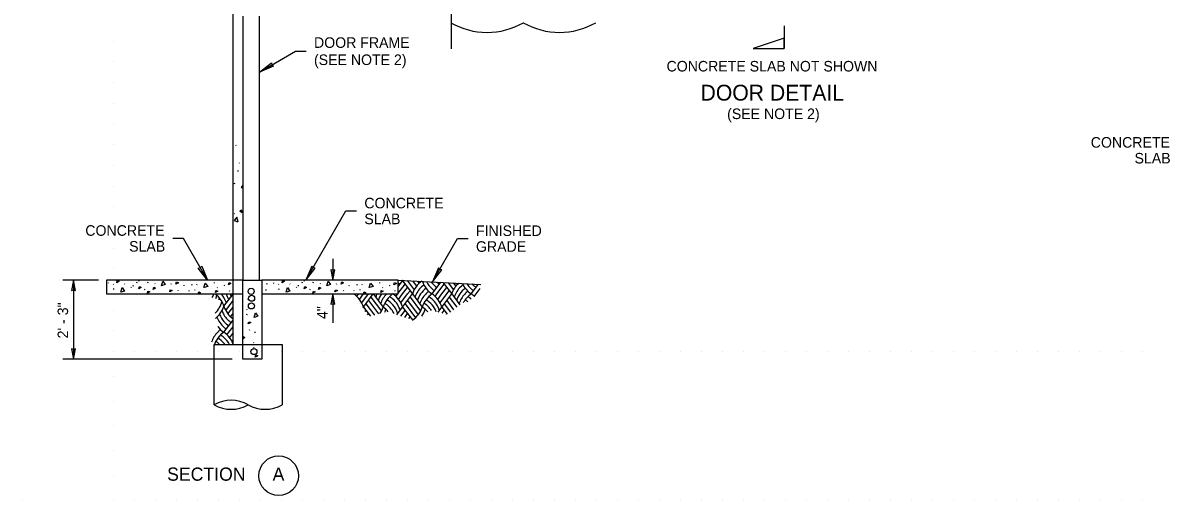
# Model space of a CAD drawing. Extents: x 99862 to 103151, y 100000 to 102076.
# Drawn here: x 99862 to 101581, y 100000 to 100723 of the extents above; entities that cross this region are included whole.
import ezdxf

# ---------------------------------------------------------------- set-up
doc = ezdxf.new("R2010")
doc.units = 0
for name, color, linetype in [('Level 1', 7, 'Continuous'), ('Level 13', 7, 'Continuous'), ('Level 15', 7, 'Continuous'), ('Level 16', 7, 'Continuous'), ('Level 17', 7, 'Continuous'), ('Level 20', 7, 'Continuous'), ('Level 22', 7, 'Continuous'), ('Level 60', 7, 'Continuous'), ('Level 8', 7, 'Continuous'), ('Level 9', 7, 'Continuous')]:
    doc.layers.add(name, color=color, linetype=linetype)

msp = doc.modelspace()

# ---------------------------------------------------------------- linework, layer by layer
at = {"layer": 'Level 1'}
for p, q in [((100000, 100695.3), (100000, 100695.3)), ((100000, 100664), (100000, 100664)), ((100000, 100632.6), (100000, 100632.6)), ((100000, 100601.3), (100000, 100601.3)), ((100000, 100569.9), (100000, 100569.9)), ((100000, 100538.6), (100000, 100538.6)), ((100000, 100507.2), (100000, 100507.2)), ((100000, 100475.8), (100000, 100475.8)), ((100000, 100444.5), (100000, 100444.5)), ((100000, 100413.1), (100000, 100413.1)), ((100000, 100381.8), (100000, 100381.8)), ((100000, 100350.4), (100000, 100350.4)), ((100000, 100319.1), (100000, 100319.1)), ((100000, 100287.7), (100000, 100287.7)), ((100000, 100256.4), (100000, 100256.4)), ((100000, 100225), (100000, 100225)), ((100031.8, 100225), (100031.8, 100225)), ((100063.6, 100225), (100063.6, 100225)), ((100095.5, 100225), (100095.5, 100225)), ((100127.3, 100225), (100127.3, 100225)), ((100159.1, 100225), (100159.1, 100225)), ((100190.9, 100225), (100190.9, 100225)), ((100222.7, 100225), (100222.7, 100225)), ((100254.5, 100225), (100254.5, 100225)), ((100286.4, 100225), (100286.4, 100225)), ((100318.2, 100225), (100318.2, 100225)), ((100350, 100225), (100350, 100225)), ((100381.8, 100225), (100381.8, 100225)), ((100413.6, 100225), (100413.6, 100225)), ((100445.5, 100225), (100445.5, 100225)), ((100477.3, 100225), (100477.3, 100225)), ((100509.1, 100225), (100509.1, 100225)), ((100540.9, 100225), (100540.9, 100225)), ((100572.7, 100225), (100572.7, 100225)), ((100604.5, 100225), (100604.5, 100225)), ((100636.4, 100225), (100636.4, 100225)), ((100668.2, 100225), (100668.2, 100225)), ((100700, 100225), (100700, 100225)), ((100731.8, 100225), (100731.8, 100225)), ((100763.6, 100225), (100763.6, 100225)), ((100795.5, 100225), (100795.5, 100225)), ((100827.3, 100225), (100827.3, 100225)), ((100859.1, 100225), (100859.1, 100225)), ((100890.9, 100225), (100890.9, 100225)), ((100922.7, 100225), (100922.7, 100225)), ((100954.5, 100225), (100954.5, 100225)), ((100986.4, 100225), (100986.4, 100225)), ((101018.2, 100225), (101018.2, 100225)), ((101050, 100225), (101050, 100225)), ((101081.8, 100225), (101081.8, 100225)), ((101113.6, 100225), (101113.6, 100225)), ((101145.5, 100225), (101145.5, 100225)), ((101177.3, 100225), (101177.3, 100225)), ((101209.1, 100225), (101209.1, 100225)), ((101240.9, 100225), (101240.9, 100225)), ((101272.7, 100225), (101272.7, 100225)), ((101304.5, 100225), (101304.5, 100225)), ((101336.4, 100225), (101336.4, 100225)), ((101368.2, 100225), (101368.2, 100225)), ((101400, 100225), (101400, 100225)), ((101431.8, 100225), (101431.8, 100225)), ((101463.6, 100225), (101463.6, 100225)), ((101495.5, 100225), (101495.5, 100225)), ((101527.3, 100225), (101527.3, 100225)), ((101559.1, 100225), (101559.1, 100225)), ((100000, 100187.5), (100000, 100187.5)), ((100000, 100150), (100000, 100150)), ((100000, 100112.5), (100000, 100112.5)), ((100000, 100075), (100000, 100075)), ((100000, 100037.5), (100000, 100037.5)), ((100000, 100000), (100000, 100000)), ((100031.8, 100000), (100031.8, 100000)), ((100063.6, 100000), (100063.6, 100000)), ((100095.5, 100000), (100095.5, 100000)), ((100127.3, 100000), (100127.3, 100000)), ((100159.1, 100000), (100159.1, 100000)), ((100190.9, 100000), (100190.9, 100000)), ((100222.7, 100000), (100222.7, 100000)), ((100254.5, 100000), (100254.5, 100000)), ((100286.4, 100000), (100286.4, 100000)), ((100318.2, 100000), (100318.2, 100000)), ((100350, 100000), (100350, 100000)), ((100381.8, 100000), (100381.8, 100000)), ((100413.6, 100000), (100413.6, 100000)), ((100445.5, 100000), (100445.5, 100000)), ((100477.3, 100000), (100477.3, 100000)), ((100509.1, 100000), (100509.1, 100000)), ((100540.9, 100000), (100540.9, 100000)), ((100572.7, 100000), (100572.7, 100000)), ((100604.5, 100000), (100604.5, 100000)), ((100636.4, 100000), (100636.4, 100000)), ((100668.2, 100000), (100668.2, 100000)), ((100700, 100000), (100700, 100000)), ((100731.8, 100000), (100731.8, 100000)), ((100763.6, 100000), (100763.6, 100000)), ((100795.5, 100000), (100795.5, 100000)), ((100827.3, 100000), (100827.3, 100000)), ((100859.1, 100000), (100859.1, 100000)), ((100890.9, 100000), (100890.9, 100000)), ((100922.7, 100000), (100922.7, 100000)), ((100954.5, 100000), (100954.5, 100000)), ((100986.4, 100000), (100986.4, 100000)), ((101018.2, 100000), (101018.2, 100000)), ((101050, 100000), (101050, 100000)), ((101081.8, 100000), (101081.8, 100000)), ((101113.6, 100000), (101113.6, 100000)), ((101145.5, 100000), (101145.5, 100000)), ((101177.3, 100000), (101177.3, 100000)), ((101209.1, 100000), (101209.1, 100000)), ((101240.9, 100000), (101240.9, 100000)), ((101272.7, 100000), (101272.7, 100000)), ((101304.5, 100000), (101304.5, 100000)), ((101336.4, 100000), (101336.4, 100000)), ((101368.2, 100000), (101368.2, 100000)), ((101400, 100000), (101400, 100000)), ((101431.8, 100000), (101431.8, 100000)), ((101463.6, 100000), (101463.6, 100000)), ((101495.5, 100000), (101495.5, 100000)), ((101527.3, 100000), (101527.3, 100000)), ((101559.1, 100000), (101559.1, 100000))]:
    msp.add_line(p, q, dxfattribs=at)
at = {"layer": 'Level 13'}
for centre in [(100208.4, 100316.2), (100209, 100305.7), (100208.8, 100294.1), (100212.5, 100224.9)]:
    msp.add_circle(centre, 4.63, dxfattribs=at)
at = {"layer": 'Level 15'}
for p, q in [((100220.9, 100648.5), (100275.7, 100680.2)), ((100275.7, 100680.2), (100291.7, 100680.2)), ((100291.5, 100333.3), (100352, 100438)), ((100352, 100438), (100368, 100438)), ((100105.8, 100396.4), (100089.8, 100396.4)), ((100142.2, 100333.3), (100105.8, 100396.4)), ((100483.4, 100330.6), (100521.2, 100396.1)), ((100521.2, 100396.1), (100537.2, 100396.1)), ((100332.3, 100365.3), (100332.3, 100333.3)), ((99977.1, 100333.3), (99922.9, 100333.3)), ((99938.9, 100333.3), (99938.9, 100213.3)), ((100332.3, 100312.4), (100332.3, 100268.4)), ((100179.5, 100213.3), (99922.9, 100213.3))]:
    msp.add_line(p, q, dxfattribs=at)
msp.add_lwpolyline([(100511.7, 101508.6), (100511.7, 101074.6), (100527.2, 101074.6), (100496.2, 101043.6), (100511.7, 101043.6), (100511.7, 100683.8)], dxfattribs=at)
for points in [[(100220.9, 100648.5), (100239.2, 100662.5), (100239.7, 100659.4), (100242.1, 100657.3)], [(100142.2, 100333.3), (100128.2, 100351.5), (100131.4, 100352.1), (100133.4, 100354.5)], [(100291.5, 100333.3), (100305.5, 100351.5), (100302.4, 100352.1), (100300.3, 100354.5)], [(100332.3, 100333.3), (100335.4, 100349), (100332.3, 100348.3), (100329.3, 100349)], [(100483.4, 100330.6), (100497.4, 100348.8), (100494.3, 100349.4), (100492.2, 100351.8)], [(99938.9, 100333.3), (99935.8, 100317.5), (99938.9, 100318.3), (99942, 100317.5)], [(100332.3, 100312.4), (100329.3, 100296.6), (100332.3, 100297.4), (100335.4, 100296.6)], [(99938.9, 100213.3), (99942, 100229), (99938.9, 100228.3), (99935.8, 100229)]]:
    msp.add_lwpolyline(points, close=True, dxfattribs=at)
at = {"layer": 'Level 16'}
for p, q in [((100185.5, 100536.5), (100185.2, 100537.7)), ((100188.9, 100497.9), (100188.6, 100499.1)), ((100183.5, 100478.7), (100183.3, 100479.9)), ((100183.1, 100434.3), (100182.5, 100433.7)), ((99991.4, 100329.2), (99992, 100328.6)), ((99999.2, 100327.3), (99999.9, 100326.7)), ((100016.3, 100327.7), (100016.9, 100327)), ((100026.6, 100321.8), (100026.8, 100323)), ((100029.5, 100324.2), (100029.8, 100325.4)), ((100035.3, 100329.2), (100035.5, 100330.4)), ((100038.2, 100331.6), (100038.5, 100332.8)), ((100051.9, 100329.3), (100052.1, 100330.5)), ((100062.2, 100328.2), (100062.9, 100327.6)), ((100086.6, 100327.9), (100087.3, 100327.3)), ((100106.6, 100324.4), (100106.8, 100325.6)), ((100118.6, 100325.7), (100118.9, 100326.9)), ((100126.1, 100325.9), (100126.3, 100327.1)), ((100152.6, 100328.6), (100152.9, 100329.8)), ((100156.9, 100322.2), (100157.5, 100321.6)), ((100167.2, 100325.5), (100167.8, 100324.9)), ((100232.4, 100327.3), (100232.7, 100328.5)), ((100242, 100329.2), (100242.6, 100328.6)), ((100249.9, 100327.3), (100250.5, 100326.7)), ((100266.9, 100327.7), (100267.5, 100327)), ((100277.2, 100321.8), (100277.4, 100323)), ((100280.2, 100324.2), (100280.4, 100325.4)), ((100285.9, 100329.2), (100286.2, 100330.4)), ((100288.9, 100331.6), (100289.1, 100332.8)), ((100302.5, 100329.3), (100302.8, 100330.5)), ((100312.9, 100328.2), (100313.5, 100327.6)), ((100337.3, 100327.9), (100337.9, 100327.3)), ((100357.2, 100324.4), (100357.5, 100325.6)), ((100369.3, 100325.7), (100369.5, 100326.9)), ((100376.7, 100325.9), (100377, 100327.1)), ((100403.3, 100328.6), (100403.5, 100329.8)), ((100407.5, 100322.2), (100408.1, 100321.6)), ((100417.8, 100325.5), (100418.5, 100324.9)), ((100000, 100319.1), (100000.3, 100320.3)), ((100046.4, 100319.6), (100047, 100319)), ((100097.8, 100317), (100098.1, 100318.2)), ((100113.5, 100317.4), (100114.2, 100316.8)), ((100123, 100317.8), (100123.3, 100319)), ((100175.8, 100316.4), (100176.1, 100317.6)), ((100203.6, 100303.8), (100203.9, 100305)), ((100231.1, 100317.6), (100231.4, 100318.8)), ((100250.6, 100319.1), (100250.9, 100320.3)), ((100297, 100319.6), (100297.7, 100319)), ((100348.5, 100317), (100348.7, 100318.2)), ((100364.2, 100317.4), (100364.8, 100316.8)), ((100373.7, 100317.8), (100373.9, 100319)), ((100426.5, 100316.4), (100426.7, 100317.6)), ((100201.2, 100289), (100201.8, 100288.4)), ((100202, 100280.8), (100202.2, 100282)), ((100205.4, 100258.3), (100205.7, 100257.2)), ((100214.3, 100253.4), (100214.6, 100254.6)), ((100211.9, 100238.7), (100212.5, 100238.1)), ((100212.7, 100230.5), (100212.9, 100231.7))]:
    msp.add_line(p, q, dxfattribs=at)
for points in [[(100190.4, 100510.9), (100190, 100510.7), (100190.4, 100510.5)], [(100195.9, 100477), (100193.5, 100473.7), (100195.9, 100473)], [(100188.5, 100421.6), (100186.6, 100428.5), (100182.8, 100423.4), (100188.4, 100421.7)], [(100194.7, 100435.9), (100193.9, 100439.3), (100191.1, 100438), (100194.7, 100435.9)], [(100004.6, 100329.3), (100005.4, 100332.7), (100008.2, 100331.4), (100004.6, 100329.3)], [(100010.8, 100315), (100012.8, 100321.9), (100016.6, 100316.7), (100011, 100315)], [(100038.2, 100320.2), (100039, 100323.5), (100041.8, 100322.2), (100038.2, 100320.2)], [(100059.8, 100319.2), (100060.6, 100322.5), (100063.5, 100321.2), (100059.8, 100319.2)], [(100072.4, 100324.7), (100074.3, 100331.6), (100078.1, 100326.4), (100072.5, 100324.7)], [(100094.4, 100327.2), (100095.2, 100330.6), (100098, 100329.3), (100094.4, 100327.2)], [(100136.9, 100321.8), (100138.9, 100328.7), (100142.6, 100323.6), (100137, 100321.9)], [(100174.2, 100326.2), (100175, 100329.6), (100177.8, 100328.3), (100174.2, 100326.2)], [(100255.3, 100329.3), (100256.1, 100332.7), (100258.9, 100331.4), (100255.3, 100329.3)], [(100261.5, 100315), (100263.4, 100321.9), (100267.2, 100316.7), (100261.6, 100315)], [(100288.8, 100320.2), (100289.6, 100323.5), (100292.5, 100322.2), (100288.8, 100320.2)], [(100310.5, 100319.2), (100311.3, 100322.5), (100314.1, 100321.2), (100310.5, 100319.2)], [(100323, 100324.7), (100325, 100331.6), (100328.7, 100326.4), (100323.1, 100324.7)], [(100345, 100327.2), (100345.8, 100330.6), (100348.6, 100329.3), (100345, 100327.2)], [(100387.5, 100321.8), (100389.5, 100328.7), (100393.3, 100323.6), (100387.7, 100321.9)], [(100424.8, 100326.2), (100425.6, 100329.6), (100428.5, 100328.3), (100424.8, 100326.2)], [(100051.2, 100313.3), (100052, 100316.6), (100054.8, 100315.3), (100051.2, 100313.3)], [(100084.9, 100315.4), (100085.7, 100318.7), (100088.5, 100317.4), (100084.9, 100315.4)], [(100128.1, 100312), (100129, 100315.3), (100131.8, 100314), (100128.1, 100312)], [(100154.2, 100314.3), (100155, 100317.7), (100157.8, 100316.4), (100154.2, 100314.3)], [(100301.9, 100313.3), (100302.7, 100316.6), (100305.5, 100315.3), (100301.9, 100313.3)], [(100335.5, 100315.4), (100336.3, 100318.7), (100339.1, 100317.4), (100335.5, 100315.4)], [(100378.8, 100312), (100379.6, 100315.3), (100382.4, 100314), (100378.8, 100312)], [(100404.8, 100314.3), (100405.6, 100317.7), (100408.4, 100316.4), (100404.8, 100314.3)], [(100204, 100266.9), (100204.8, 100270.2), (100207.7, 100268.9), (100204, 100266.9)], [(100212.8, 100276.8), (100214.8, 100283.6), (100218.5, 100278.5), (100212.9, 100276.8)], [(100196.2, 100248), (100198.9, 100246.2), (100196.3, 100244.2)], [(100214.7, 100216.6), (100215.5, 100219.9), (100218.4, 100218.6), (100214.7, 100216.6)]]:
    msp.add_lwpolyline(points, dxfattribs=at)
at = {"layer": 'Level 17'}
for p, q in [((100220.9, 100333.3), (100220.9, 100733.3)), ((100180.9, 100235.5), (100180.9, 100333.3))]:
    msp.add_line(p, q, dxfattribs=at)
for points in [[(100195.9, 100333.3), (100180.9, 100333.3), (100180.9, 100743.3)], [(100195.9, 100733.3), (100195.9, 100333.3)], [(100195.9, 100333.3), (99989.1, 100333.3), (99989.1, 100312.4), (100196.1, 100312.4)], [(100195.9, 100213.3), (100195.9, 100333.3), (100224.5, 100333.3), (100224.5, 100213.3), (100195.9, 100213.3)], [(100152.4, 100144.3), (100152.4, 100235.5), (100255.3, 100235.5), (100255.3, 100144.3)]]:
    msp.add_lwpolyline(points, dxfattribs=at)
msp.add_lwpolyline([(100431.5, 100333.3), (100224.5, 100333.3), (100224.5, 100312.4), (100431.5, 100312.4)], close=True, dxfattribs=at)
for centre, radius, start, end in [((100566, 100818.7), 110.1, 240, 300), ((100676, 100818.7), 110.1, 240, 300), ((100178.1, 100099.7), 51.4, 60, 120), ((100178.1, 100188.8), 51.4, 240, 300), ((100229.6, 100188.8), 51.4, 240, 300)]:
    msp.add_arc(centre, radius, start, end, dxfattribs=at)
at = {"layer": 'Level 22'}
for p, q in [((100431.5, 100323.2), (100438.1, 100332)), ((100431.5, 100313.3), (100441.9, 100327)), ((100438.1, 100332), (100438.8, 100332.9)), ((100438.1, 100332), (100453, 100312.2)), ((100438.1, 100312.2), (100445.6, 100322.1)), ((100445.1, 100332.5), (100455.7, 100318.5)), ((100452.9, 100332.1), (100459.1, 100323.8)), ((100460.6, 100331.7), (100463.2, 100328.3)), ((100482.7, 100312.2), (100496, 100329.9)), ((100490.1, 100312.2), (100501.2, 100327)), ((100497.5, 100312.2), (100505, 100322.1)), ((100499.2, 100329.7), (100512.4, 100312.2)), ((100506.9, 100329.3), (100515.1, 100318.5)), ((100514.7, 100328.9), (100518.5, 100323.8)), ((100522.4, 100328.5), (100522.6, 100328.3)), ((100542.1, 100312.2), (100553.1, 100326.9)), ((100167.1, 100293.7), (100180.9, 100312.1)), ((100368.5, 100308.5), (100371.3, 100312.2)), ((100371.3, 100312.2), (100371.3, 100312.2)), ((100372.6, 100304), (100378.7, 100312.2)), ((100376.1, 100298.7), (100386.2, 100312.2)), ((100378.7, 100292.4), (100393.6, 100312.2)), ((100378.7, 100312.2), (100378.8, 100312.2)), ((100386.2, 100312.2), (100386.2, 100312.2)), ((100389.9, 100307.2), (100405.8, 100286.1)), ((100393.5, 100312.3), (100393.6, 100312.2)), ((100393.6, 100312.2), (100408.4, 100292.4)), ((100423.3, 100312.2), (100423.4, 100312.3)), ((100427.9, 100308.5), (100430.7, 100312.2)), ((100430.7, 100312.2), (100430.9, 100312.4)), ((100432, 100304), (100438.1, 100312.2)), ((100435.5, 100298.7), (100445.6, 100312.2)), ((100438.1, 100292.4), (100453, 100312.2)), ((100445.6, 100312.2), (100449.3, 100317.1)), ((100449.3, 100307.2), (100465.2, 100286.1)), ((100453, 100312.2), (100467.8, 100292.4)), ((100487.3, 100308.5), (100490.1, 100312.2)), ((100491.4, 100304), (100497.5, 100312.2)), ((100494.9, 100298.7), (100505, 100312.2)), ((100497.5, 100292.4), (100512.4, 100312.2)), ((100505, 100312.2), (100508.7, 100317.1)), ((100508.7, 100307.2), (100520, 100292.2)), ((100512.4, 100312.2), (100524.6, 100295.9)), ((100546.7, 100308.5), (100549.5, 100312.2)), ((100549.5, 100312.2), (100555.8, 100320.6)), ((100169.8, 100287.3), (100180.9, 100302.2)), ((100173.2, 100282), (100180.9, 100292.3)), ((100377.8, 100291.1), (100378.7, 100292.4)), ((100378.7, 100292.4), (100389.3, 100278.4)), ((100381.2, 100285.8), (100382.5, 100287.4)), ((100382.5, 100297.3), (100395.4, 100280.1)), ((100386.2, 100302.3), (100401.5, 100281.9)), ((100429.5, 100280.8), (100438.1, 100292.4)), ((100435.4, 100278.8), (100441.9, 100287.4)), ((100438.1, 100292.4), (100452.8, 100272.9)), ((100441.9, 100297.3), (100457.6, 100276.3)), ((100445.6, 100302.3), (100461.7, 100280.7)), ((100491.8, 100284.7), (100497.5, 100292.4)), ((100497.5, 100292.4), (100505.7, 100281.5)), ((100498.1, 100283.3), (100501.2, 100287.4)), ((100501.2, 100297.3), (100510.8, 100284.6)), ((100505, 100302.3), (100515.4, 100288.4)), ((100167.1, 100254.1), (100180.9, 100272.5)), ((100177.3, 100277.6), (100180.9, 100282.4)), ((100384.7, 100280.5), (100386.2, 100282.5)), ((100441.3, 100276.8), (100445.6, 100282.5)), ((100447.2, 100274.8), (100449.3, 100277.5)), ((100504.4, 100281.8), (100505, 100282.5)), ((100171.7, 100250.4), (100174.5, 100254.1)), ((100174.5, 100254.1), (100180.9, 100262.6)), ((100175.8, 100245.9), (100180.9, 100252.7)), ((100179.3, 100240.6), (100180.9, 100242.8))]:
    msp.add_line(p, q, dxfattribs=at)
for centre, start, end in [((99967.9, 100302.1), 56.0952, 56.0963), ((100218.6, 100302.1), 56.0952, 56.0963), ((100455.4, 100358.2), 230.574, 236.0964), ((100459.1, 100363.2), 233.4561, 236.0964), ((100488.8, 100300.8), 125.4423, 162.3566), ((100492.5, 100295.8), 126.3063, 154.2266), ((100503.6, 100343.4), 198.6509, 236.0964), ((100507.4, 100348.3), 207.3703, 228.9599), ((100511.1, 100353.3), 216.9567, 220.9416), ((100511.1, 100353.3), 220.9415, 236.0964), ((100514.8, 100358.2), 228.1518, 236.0964), ((100548.2, 100300.8), 132.4757, 162.3566), ((100551.9, 100295.8), 126.3063, 154.2266), ((100563, 100343.4), 203.8023, 236.0964), ((100566.8, 100348.3), 212.9827, 228.9599), ((100570.5, 100353.3), 223.3983, 236.0964), ((100116.4, 100324.8), 331.5641, 340.7064), ((100131.3, 100282.3), 32.4879, 52.8045), ((100120.1, 100319.9), 336.9798, 345.0113), ((100123.9, 100314.9), 342.3545, 346.3199), ((100135, 100287.2), 31.3316, 41.6055), ((100135, 100287.2), 17.6434, 31.3317), ((100138.7, 100292.2), 17.6434, 32.5049), ((100142.4, 100297.1), 17.6434, 23.6581), ((100342.9, 100281), 17.6434, 56.0948), ((100429.4, 100300.8), 162.227, 162.3566), ((100433.1, 100295.8), 154.2265, 162.3566), ((100433.1, 100295.8), 154.063, 154.2266), ((100436.8, 100290.9), 145.491, 162.3566), ((100440.5, 100285.9), 135.7127, 162.3566), ((100436.8, 100290.9), 145.2788, 145.4911), ((100444.3, 100281), 123.9036, 162.3566), ((100440.5, 100285.9), 135.4226, 135.7128), ((100398.6, 100276), 48.9597, 58.5465), ((100444.3, 100343.4), 235.6582, 236.0964), ((100402.3, 100281), 17.6434, 56.0963), ((100398.6, 100276), 17.6434, 48.9597), ((100492.5, 100295.8), 154.2265, 162.3566), ((100496.2, 100290.9), 145.491, 162.3566), ((100499.9, 100285.9), 135.7127, 162.3566), ((100496.2, 100290.9), 127.1006, 145.4911), ((100503.6, 100281), 123.9036, 162.3566), ((100499.9, 100285.9), 126.331, 135.7128), ((100458, 100276), 48.9597, 58.5465), ((100507.4, 100348.3), 228.9599, 236.0964), ((100461.7, 100281), 17.6434, 56.0963), ((100458, 100276), 17.6434, 48.9597), ((100551.9, 100295.8), 154.2265, 162.3566), ((100555.6, 100290.9), 145.491, 162.3566), ((100559.3, 100285.9), 135.7127, 162.3566), ((100555.6, 100290.9), 127.1006, 145.4911), ((100563, 100281), 123.9036, 151.2939), ((100559.3, 100285.9), 126.331, 135.7128), ((100517.4, 100276), 48.9597, 58.5465), ((100566.8, 100348.3), 228.9599, 236.0964), ((100521.1, 100281), 46.5026, 56.0963), ((100127.6, 100310), 314.0469, 345.7713), ((100131.3, 100305), 307.6535, 342.3566), ((100131.3, 100282.3), 17.6434, 31.7715), ((100202.9, 100305), 197.6435, 234.1378), ((100372.6, 100303.8), 325.581, 342.3566), ((100387.5, 100261.2), 39.8941, 56.0964), ((100391.2, 100266.1), 31.3316, 58.4874), ((100376.3, 100298.8), 337.962, 345.0113), ((100394.9, 100271.1), 40.9413, 59.3021), ((100394.9, 100271.1), 17.6434, 40.9414), ((100432, 100303.8), 304.3124, 342.3566), ((100435.7, 100298.8), 327.3344, 345.0113), ((100446.9, 100261.2), 39.2778, 56.0964), ((100450.6, 100266.1), 33.8326, 58.4874), ((100454.3, 100271.1), 40.9413, 59.3021), ((100454.3, 100271.1), 22.3332, 40.9414), ((100513.7, 100271.1), 51.5799, 59.3021), ((100191.8, 100290.2), 200.2432, 228.9599), ((100195.5, 100295.1), 201.4344, 220.9416), ((100199.2, 100300.1), 200.8778, 211.332), ((100199.2, 100300.1), 211.3319, 236.0964), ((100195.5, 100295.1), 220.9415, 236.0964), ((100391.2, 100266.1), 25.4574, 31.3317), ((100439.5, 100293.9), 346.3147, 346.3199), ((100184.3, 100227.8), 135.7127, 162.3566), ((100188, 100222.9), 123.9036, 162.3566), ((100184.3, 100227.8), 131.7323, 135.7128), ((100188, 100285.2), 216.226, 236.0964), ((100180.6, 100232.8), 127.1006, 127.3145), ((100184.3, 100227.8), 126.331, 130.9808), ((100191.8, 100290.2), 228.9599, 236.0964), ((100146.1, 100222.9), 22.3436, 56.0963), ((100135, 100208), 47.1051, 58.4874), ((100138.7, 100213), 40.9413, 59.3021), ((100142.4, 100217.9), 48.9597, 58.5465), ((100142.4, 100217.9), 27.9799, 48.9597), ((100138.7, 100213), 36.9331, 40.9414)]:
    msp.add_arc(centre, 37.6, start, end, dxfattribs=at)
at = {"layer": 'Level 60'}
msp.add_line((99862, 99999.5), (99862, 99999.5), dxfattribs=at)
at = {"layer": 'Level 8'}
msp.add_line((100431.5, 100333.3), (100556.8, 100326.7), dxfattribs=at)
at = {"layer": 'Level 9'}
msp.add_line((101016.5, 100718.4), (101016.5, 100684.4), dxfattribs=at)
msp.add_lwpolyline([(101016.5, 100700), (100969.6, 100684.4), (101016.5, 100684.4)], close=True, dxfattribs=at)
msp.add_circle((100250.1, 100036.8), 30, dxfattribs=at)

# ---------------------------------------------------------------- texts
at = {"layer": 'Level 20'}
for s, height, p in [('DOOR FRAME', 16, (100303.7, 100685.2)), ('(SEE NOTE 2)', 16, (100303.7, 100659.2)), ('CONCRETE SLAB NOT SHOWN', 16, (100838.2, 100649.4)), ('DOOR DETAIL', 24, (100889.7, 100605.3)), ('(SEE NOTE 2)', 16, (100930, 100577.3)), ('CONCRETE', 16, (100380, 100442)), ('SLAB', 16, (100380, 100418)), ('FINISHED', 16, (100549.2, 100400.1)), ('GRADE', 16, (100549.2, 100376.1)), ('SECTION', 20, (100081, 100029.2)), ('A', 20, (100240.9, 100029.2))]:
    msp.add_text(s, height=height, dxfattribs=at).set_placement(p)
for s, rotation, p in [('CONCRETE', 360, (101481.3, 100534)), ('SLAB', 360, (101547.7, 100510)), ('CONCRETE', 360, (99957, 100400.4)), ('SLAB', 360, (100023.4, 100376.4)), ('2\' - 3"', 90, (99930.9, 100244.9)), ('4"', 90, (100324.3, 100274.2))]:
    msp.add_text(s, height=16, rotation=rotation, dxfattribs=at).set_placement(p)

doc.saveas('drawing.dxf')
